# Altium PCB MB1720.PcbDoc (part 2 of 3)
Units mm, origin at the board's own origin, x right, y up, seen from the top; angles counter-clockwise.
Board outline 62.4 x 34.09 mm, 4 copper layers (Top Layer, MidLayer 1, MidLayer 2, Bottom Layer), stack 1.594 mm thick; 82 components, 66 nets, 241 pads, 1258 vias.
Unrouted connection lines stored in the file: 1.
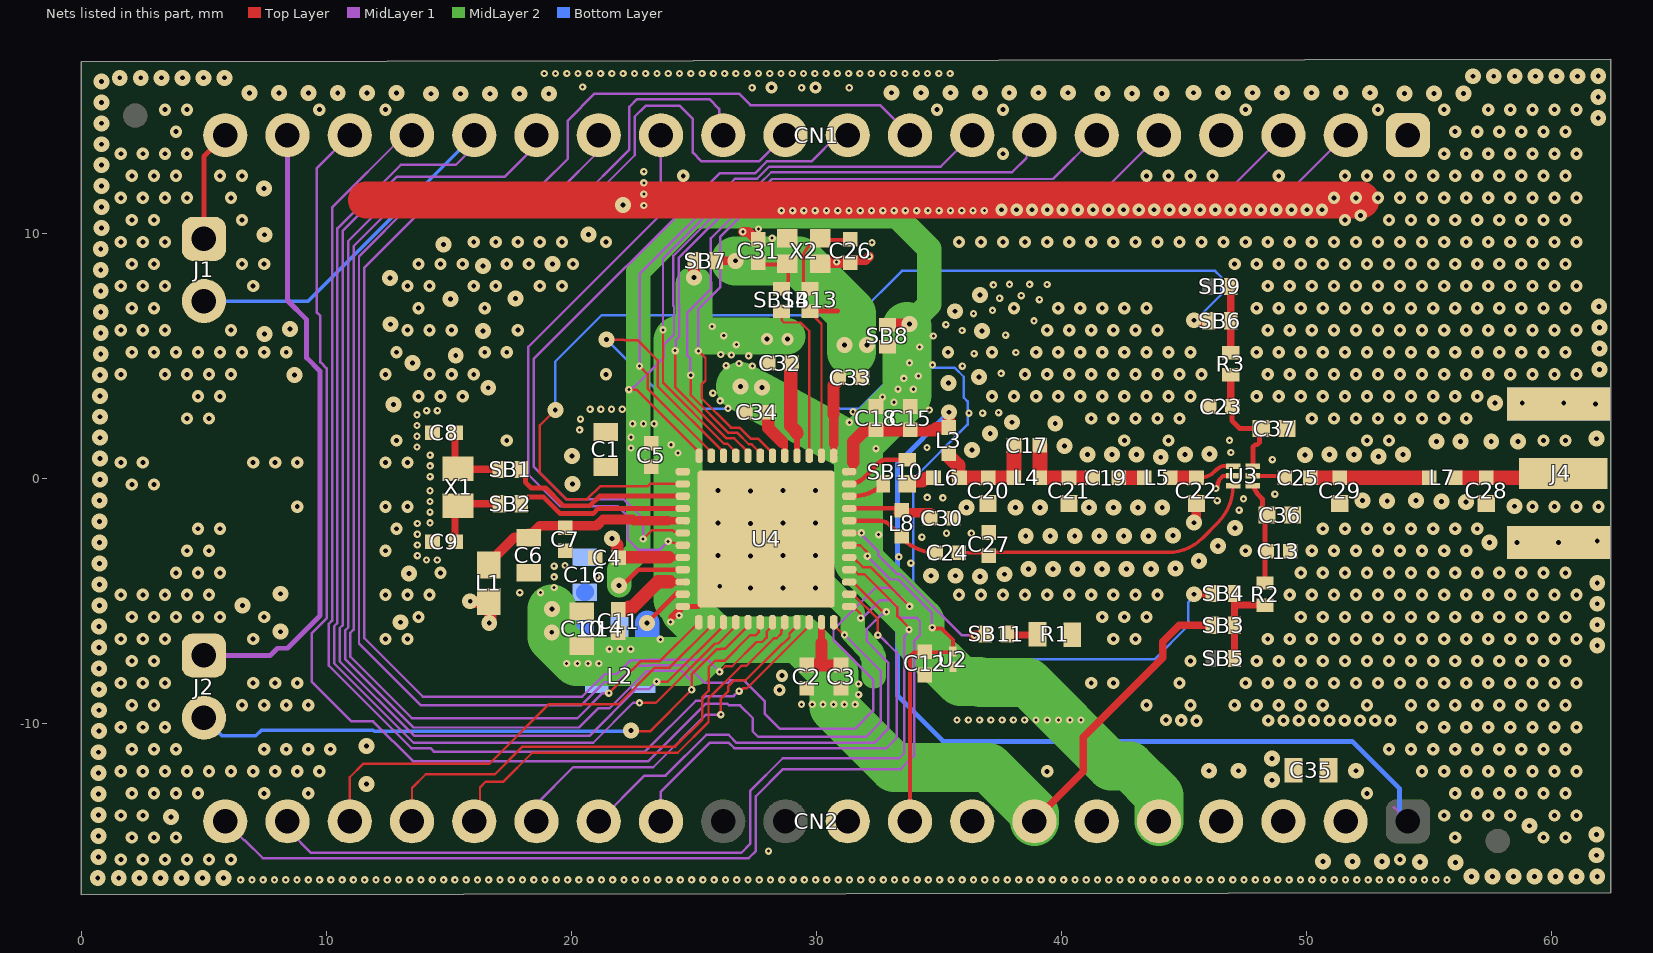
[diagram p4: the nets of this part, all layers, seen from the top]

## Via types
v1: diameter 0.5, hole 0.2, Top Layer to Bottom Layer, 667 vias
v2: diameter 0.3, hole 0.125, Top Layer to MidLayer 1, 336 vias
v3: diameter 0.65, hole 0.2, Top Layer to Bottom Layer, 255 vias

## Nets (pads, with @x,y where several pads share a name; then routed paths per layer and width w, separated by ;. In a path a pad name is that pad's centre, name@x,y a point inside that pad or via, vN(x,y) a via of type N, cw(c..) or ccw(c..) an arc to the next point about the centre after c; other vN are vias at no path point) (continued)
GND: C1.1 C2.1 C3.1 C4.1 C5.1 C6.2 C7.2 C8.2 C9.2 C10.2 C11.2 C12.2 C13.1 C14.2 C15.2 C16.2 C18.1 C20.2 C21.1 C22.1 C23.1 C26.2 C27.1 C28.2 C29.2 C30.1 C31.2 C32.1 C33.1 C34.1 C35.2 C36.1 C37.1 CN1.1 CN1.4 CN2.2 CN2.4 CN2.6 CN2.8 CN2.10 J4.2 R1.1 U2.2 U3.2 U4.48 U4.49 X2.2 X2.4 | length 57
  Top Layer w0.1: CN1.4@46.487,13.977 CN1.4@46.51,14
  Top Layer w0.15: U3.2@46.706,0.1 U3.2@47,0.1
  Top Layer w0.18: v2@46.362,-0.306 cw(c46.706,-0.306) 46.42,-0.116 46.42,-0.072 46.584,0.092 46.706,0.092 U3.2@46.706,0.1
  Top Layer w0.2: U4.48@24.541,-5.231 25.166,-5.231 27.918,-2.479 U4.49@27.94,-2.479
  Top Layer w0.3: 24.1,-5.671 24.391,-5.381 24.391,-5.231 U4.48@24.541,-5.231 ; X2.4@30.15,8.75 X2.4@30.225,8.825
  Top Layer w0.4: v2(26.99,10.061) 27.214,10.061 27.55,9.725 C31.2@27.625,9.725 ; C26.2@31.375,8.825 31.45,8.9 32.004,8.9 v2(32.153,9.049) ; v3@45.481,-1.602 45.481,-1.51 45.493,-1.498 45.493,-0.832 C22.1@45.5,-0.825
  Top Layer w0.5: X2.4@30.225,8.825 C26.2@31.375,8.825 ; C35.2@50.884,-12.056 C35.2@50.884,-11.918 ; CN2.2@51.341,-13.751 CN2.2@51.59,-14
  Top Layer w1.5: 11.629,11.36 16.197,11.359 ; 15.984,11.359 v1@52.229,11.359
  MidLayer 2 w1: 29.684,-3.689 31.485,-5.491 31.485,-6.267 32.252,-7.096 32.252,-7.211 32.325,-7.285 32.325,-8.08 ; CN2.6@41.43,-14 CN2.6@41.43,-13.661
  other v1: 1.608,-15.557 2.508,-15.557 3.408,-15.557 4.308,-15.557 5.208,-15.557 6.108,-15.557 53.809,-15.557 2.058,-14.657 2.958,-14.657 3.858,-14.657 56.059,-14.657 59.659,-14.657 60.559,-14.657 1.608,-13.757 2.508,-13.757 55.609,-13.757 56.509,-13.757 57.409,-13.757 58.309,-13.757 60.109,-13.757 61.009,-13.757 2.058,-12.857 2.958,-12.857 3.858,-12.857 4.758,-12.857 7.458,-12.857 9.258,-12.857 52.459,-12.857 56.059,-12.857 56.959,-12.857 57.859,-12.857 58.759,-12.857 59.659,-12.857 60.559,-12.857 1.608,-11.957 2.508,-11.957 3.408,-11.957 4.308,-11.957 5.208,-11.957 6.108,-11.957 7.008,-11.957 7.908,-11.957 8.808,-11.957 9.708,-11.957 39.409,-11.957 54.709,-11.957 55.609,-11.957 56.509,-11.957 57.409,-11.957 58.309,-11.957 59.209,-11.957 60.109,-11.957 61.009,-11.957 2.058,-11.057 2.958,-11.057 3.858,-11.057 7.458,-11.057 8.358,-11.057 9.258,-11.057 10.158,-11.057 53.359,-11.057 54.259,-11.057 55.159,-11.057 56.059,-11.057 56.959,-11.057 57.859,-11.057 58.759,-11.057 59.659,-11.057 60.559,-11.057 1.608,-10.157 2.508,-10.157 3.408,-10.157 54.709,-10.157 55.609,-10.157 56.509,-10.157 57.409,-10.157 58.309,-10.157 59.209,-10.157 60.109,-10.157 61.009,-10.157 45.505,-9.896 44.258,-9.86 44.882,-9.878 48.432,-9.88 49.055,-9.88 49.678,-9.88 50.302,-9.88 50.925,-9.88 51.548,-9.88 52.171,-9.88 52.794,-9.88 53.417,-9.88 2.058,-9.257 2.958,-9.257 6.558,-9.257 7.458,-9.257 8.358,-9.257 9.258,-9.257 43.459,-9.257 45.259,-9.257 47.059,-9.257 47.959,-9.257 48.859,-9.257 49.759,-9.257 50.659,-9.257 52.459,-9.257 54.259,-9.257 55.159,-9.257 56.059,-9.257 56.959,-9.257 57.859,-9.257 58.759,-9.257 59.659,-9.257 60.559,-9.257 1.608,-8.357 2.508,-8.357 3.408,-8.357 7.008,-8.357 7.908,-8.357 8.808,-8.357 41.209,-8.357 42.109,-8.357 44.809,-8.357 47.509,-8.357 48.409,-8.357 49.309,-8.357 50.209,-8.357 51.109,-8.357 52.009,-8.357 52.909,-8.357 53.809,-8.357 54.709,-8.357 55.609,-8.357 56.509,-8.357 57.409,-8.357 58.309,-8.357 59.209,-8.357 60.109,-8.357 61.009,-8.357 2.058,-7.457 2.958,-7.457 45.259,-7.457 47.959,-7.457 48.859,-7.457 49.759,-7.457 50.659,-7.457 51.559,-7.457 52.459,-7.457 53.359,-7.457 54.259,-7.457 55.159,-7.457 56.059,-7.457 56.959,-7.457 57.859,-7.457 58.759,-7.457 59.659,-7.457 60.559,-7.457 1.608,-6.557 2.508,-6.557 3.408,-6.557 7.008,-6.557 12.408,-6.557 13.309,-6.557 42.109,-6.557 43.009,-6.557 48.409,-6.557 49.309,-6.557 50.209,-6.557 51.109,-6.557 52.009,-6.557 52.909,-6.557 53.809,-6.557 54.709,-6.557 55.609,-6.557 56.509,-6.557 57.409,-6.557 58.309,-6.557 59.209,-6.557 60.109,-6.557 61.009,-6.557 2.058,-5.657 2.958,-5.657 3.858,-5.657 4.758,-5.657 5.658,-5.657 7.458,-5.657 13.759,-5.657 41.659,-5.657 42.559,-5.657 43.459,-5.657 49.759,-5.657 50.659,-5.657 51.559,-5.657 52.459,-5.657 53.359,-5.657 54.259,-5.657 55.159,-5.657 56.059,-5.657 56.959,-5.657 57.859,-5.657 58.759,-5.657 59.659,-5.657 60.559,-5.657 1.608,-4.757 2.508,-4.757 3.408,-4.757 4.308,-4.757 5.208,-4.757 12.408,-4.757 13.309,-4.757 14.209,-4.757 35.809,-4.757 36.709,-4.757 37.609,-4.757 38.509,-4.757 39.409,-4.757 40.309,-4.757 41.209,-4.757 42.109,-4.757 43.009,-4.757 43.909,-4.757 49.309,-4.757 50.209,-4.757 51.109,-4.757 52.009,-4.757 52.909,-4.757 53.809,-4.757 54.709,-4.757 55.609,-4.757 56.509,-4.757 57.409,-4.757 58.309,-4.757 59.209,-4.757 60.109,-4.757 61.009,-4.757 3.858,-3.857 4.758,-3.857 5.658,-3.857 14.659,-3.857 49.759,-3.857 50.659,-3.857 51.559,-3.857 52.459,-3.857 53.359,-3.857 54.259,-3.857 55.159,-3.857 56.059,-3.857 56.959,-3.857 57.859,-3.857 58.759,-3.857 59.659,-3.857 60.559,-3.857 4.308,-2.957 5.208,-2.957 12.408,-2.957 47.509,-2.957 50.209,-2.957 51.109,-2.957 52.009,-2.957 52.909,-2.957 53.809,-2.957 54.709,-2.957 55.609,-2.957 56.509,-2.957 4.758,-2.057 5.658,-2.057 12.859,-2.057 50.659,-2.057 51.559,-2.057 52.459,-2.057 53.359,-2.057 54.259,-2.057 55.159,-2.057 56.059,-2.057 56.959,-2.057 8.808,-1.157 12.408,-1.157 13.309,-1.157 59.209,-1.157 60.109,-1.157 61.009,-1.157 61.909,-1.157 2.058,-0.257 2.958,-0.257 1.608,0.643 2.508,0.643 7.008,0.643 7.908,0.643 8.808,0.643 12.408,0.643 13.309,0.643 12.859,1.543 17.359,1.543 42.559,1.543 44.359,1.543 52.459,1.543 53.359,1.543 59.659,1.543 60.559,1.543 4.308,2.443 5.208,2.443 41.209,2.443 42.109,2.443 43.009,2.443 43.909,2.443 44.809,2.443 50.209,2.443 51.109,2.443 52.009,2.443 52.909,2.443 53.809,2.443 54.709,2.443 55.609,2.443 56.509,2.443 4.758,3.343 5.658,3.343 13.759,3.343 14.659,3.343 15.559,3.343 37.159,3.343 38.059,3.343 38.959,3.343 39.859,3.343 40.759,3.343 41.659,3.343 42.559,3.343 43.459,3.343 44.359,3.343 45.259,3.343 47.959,3.343 48.859,3.343 49.759,3.343 50.659,3.343 51.559,3.343 52.459,3.343 53.359,3.343 54.259,3.343 55.159,3.343 56.059,3.343 56.959,3.343 1.608,4.243 3.408,4.243 4.308,4.243 5.208,4.243 6.108,4.243 12.408,4.243 14.209,4.243 15.109,4.243 16.009,4.243 21.409,4.243 38.509,4.243 39.409,4.243 40.309,4.243 41.209,4.243 42.109,4.243 43.009,4.243 43.909,4.243 44.809,4.243 45.709,4.243 48.409,4.243 49.309,4.243 50.209,4.243 51.109,4.243 52.009,4.243 52.909,4.243 53.809,4.243 54.709,4.243 55.609,4.243 56.509,4.243 57.409,4.243 58.309,4.243 59.209,4.243 60.109,4.243 61.009,4.243 2.058,5.143 2.958,5.143 3.858,5.143 4.758,5.143 5.658,5.143 6.558,5.143 7.458,5.143 8.358,5.143 12.859,5.143 16.459,5.143 17.359,5.143 35.359,5.143 37.159,5.143 38.959,5.143 39.859,5.143 40.759,5.143 41.659,5.143 42.559,5.143 43.459,5.143 44.359,5.143 45.259,5.143 47.959,5.143 48.859,5.143 49.759,5.143 50.659,5.143 51.559,5.143 52.459,5.143 53.359,5.143 54.259,5.143 55.159,5.143 56.059,5.143 56.959,5.143 57.859,5.143 58.759,5.143 59.659,5.143 60.559,5.143 1.608,6.043 2.508,6.043 3.408,6.043 6.108,6.043 13.309,6.043 14.209,6.043 15.109,6.043 17.809,6.043 39.409,6.043 40.309,6.043 41.209,6.043 42.109,6.043 43.009,6.043 43.909,6.043 48.409,6.043 49.309,6.043 50.209,6.043 51.109,6.043 52.009,6.043 52.909,6.043 53.809,6.043 54.709,6.043 55.609,6.043 56.509,6.043 57.409,6.043 58.309,6.043 59.209,6.043 60.109,6.043 61.009,6.043 2.058,6.943 2.958,6.943 13.759,6.943 16.459,6.943 38.059,6.943 39.859,6.943 40.759,6.943 41.659,6.943 42.559,6.943 43.459,6.943 47.959,6.943 48.859,6.943 49.759,6.943 50.659,6.943 51.559,6.943 52.459,6.943 53.359,6.943 54.259,6.943 55.159,6.943 56.059,6.943 56.959,6.943 57.859,6.943 58.759,6.943 59.659,6.943 60.559,6.943 1.608,7.843 2.508,7.843 3.408,7.843 7.008,7.843 13.309,7.843 14.209,7.843 16.009,7.843 16.909,7.843 18.709,7.843 19.609,7.843 48.409,7.843 49.309,7.843 50.209,7.843 51.109,7.843 52.009,7.843 52.909,7.843 53.809,7.843 54.709,7.843 55.609,7.843 56.509,7.843 57.409,7.843 58.309,7.843 59.209,7.843 60.109,7.843 61.009,7.843 2.058,8.743 2.958,8.743 6.558,8.743 7.458,8.743 13.759,8.743 14.659,8.743 15.559,8.743 17.359,8.743 18.259,8.743 20.059,8.743 47.059,8.743 47.959,8.743 48.859,8.743 49.759,8.743 50.659,8.743 51.559,8.743 52.459,8.743 53.359,8.743 54.259,8.743 55.159,8.743 56.059,8.743 56.959,8.743 57.859,8.743 58.759,8.743 59.659,8.743 60.559,8.743 1.608,9.643 2.508,9.643 3.408,9.643 16.009,9.643 16.909,9.643 17.809,9.643 18.709,9.643 19.609,9.643 21.409,9.643 35.809,9.643 36.709,9.643 37.609,9.643 38.509,9.643 39.409,9.643 40.309,9.643 41.209,9.643 42.109,9.643 43.009,9.643 43.909,9.643 44.809,9.643 45.709,9.643 46.609,9.643 47.509,9.643 48.409,9.643 49.309,9.643 50.209,9.643 51.109,9.643 52.009,9.643 52.909,9.643 53.809,9.643 54.709,9.643 55.609,9.643 56.509,9.643 57.409,9.643 58.309,9.643 59.209,9.643 60.109,9.643 61.009,9.643 2.058,10.543 2.958,10.543 6.558,10.543 51.559,10.543 53.359,10.543 54.259,10.543 55.159,10.543 56.059,10.543 56.959,10.543 57.859,10.543 58.759,10.543 59.659,10.543 60.559,10.543 52.202,10.719 37.542,10.956 38.165,10.956 38.788,10.956 39.412,10.956 40.035,10.956 40.658,10.956 41.281,10.956 41.904,10.956 42.527,10.956 43.15,10.956 43.773,10.956 44.397,10.956 45.02,10.956 45.643,10.956 46.266,10.956 46.889,10.956 47.512,10.956 48.135,10.956 48.759,10.956 49.382,10.956 50.005,10.956 50.628,10.956 1.608,11.443 2.508,11.443 3.408,11.443 4.308,11.443 6.108,11.443 51.109,11.443 52.009,11.443 52.909,11.443 53.809,11.443 54.709,11.443 55.609,11.443 56.509,11.443 57.409,11.443 58.309,11.443 59.209,11.443 60.109,11.443 61.009,11.443 2.058,12.343 2.958,12.343 3.858,12.343 5.658,12.343 6.558,12.343 24.559,12.343 43.459,12.343 44.359,12.343 45.259,12.343 46.159,12.343 48.859,12.343 51.559,12.343 52.459,12.343 53.359,12.343 54.259,12.343 55.159,12.343 56.059,12.343 56.959,12.343 57.859,12.343 58.759,12.343 59.659,12.343 60.559,12.343 1.608,13.243 2.508,13.243 3.408,13.243 4.308,13.243 37.609,13.243 55.609,13.243 56.509,13.243 57.409,13.243 58.309,13.243 59.209,13.243 60.109,13.243 61.009,13.243 3.858,14.143 56.059,14.143 56.959,14.143 57.859,14.143 58.759,14.143 59.659,14.143 60.559,14.143 3.408,15.043 4.308,15.043 9.708,15.043 12.408,15.043 34.909,15.043 37.609,15.043 47.509,15.043 52.909,15.043 55.609,15.043 57.409,15.043 58.309,15.043 59.209,15.043 60.109,15.043 61.009,15.043 28.159,15.943 29.959,15.943
  other v2: 6.5,-16.387 6.96,-16.387 7.42,-16.387 7.88,-16.387 8.34,-16.387 8.8,-16.387 9.26,-16.387 9.72,-16.387 10.18,-16.387 10.64,-16.387 11.1,-16.387 11.56,-16.387 12.02,-16.387 12.48,-16.387 12.94,-16.387 13.4,-16.387 13.86,-16.387 14.32,-16.387 14.78,-16.387 15.24,-16.387 15.7,-16.387 16.161,-16.387 16.621,-16.387 17.081,-16.387 17.541,-16.387 18.001,-16.387 18.461,-16.387 18.921,-16.387 19.381,-16.387 19.841,-16.387 20.301,-16.387 20.761,-16.387 21.221,-16.387 21.681,-16.387 22.141,-16.387 22.601,-16.387 23.061,-16.387 23.521,-16.387 23.981,-16.387 24.441,-16.387 24.901,-16.387 25.361,-16.387 25.821,-16.387 26.281,-16.387 26.742,-16.387 27.202,-16.387 27.662,-16.387 28.122,-16.387 28.582,-16.387 29.042,-16.387 29.502,-16.387 29.962,-16.387 30.422,-16.387 30.882,-16.387 31.342,-16.387 31.802,-16.387 32.262,-16.387 32.722,-16.387 33.182,-16.387 33.642,-16.387 34.102,-16.387 34.562,-16.387 35.022,-16.387 35.482,-16.387 35.942,-16.387 36.402,-16.387 36.863,-16.387 37.323,-16.387 37.783,-16.387 38.243,-16.387 38.703,-16.387 39.163,-16.387 39.623,-16.387 40.083,-16.387 40.543,-16.387 41.003,-16.387 41.463,-16.387 41.923,-16.387 42.383,-16.387 42.843,-16.387 43.303,-16.387 43.763,-16.387 44.223,-16.387 44.683,-16.387 45.143,-16.387 45.603,-16.387 46.063,-16.387 46.523,-16.387 46.984,-16.387 47.444,-16.387 47.904,-16.387 48.364,-16.387 48.824,-16.387 49.284,-16.387 49.744,-16.387 50.204,-16.387 50.664,-16.387 51.124,-16.387 51.584,-16.387 52.044,-16.387 52.504,-16.387 52.964,-16.387 53.424,-16.387 53.884,-16.387 54.344,-16.387 54.804,-16.387 55.264,-16.387 55.724,-16.387 28.038,-15.213 35.732,-9.861 36.192,-9.861 36.652,-9.861 37.112,-9.861 37.572,-9.861 38.032,-9.861 38.492,-9.861 38.952,-9.861 39.412,-9.861 39.872,-9.861 40.332,-9.861 40.792,-9.861 29.385,-9.223 29.822,-9.223 30.26,-9.223 30.697,-9.223 31.134,-9.223 31.572,-9.223 31.718,-8.832 31.718,-8.396 19.803,-7.561 20.24,-7.561 20.678,-7.561 21.115,-7.561 21.543,-6.969 21.98,-6.969 22.417,-6.969 23.627,-6.571 24.043,-5.865 24.391,-5.6 17.887,-4.666 18.737,-4.666 19.293,-4.458 19.293,-4.021 21.045,-3.996 19.293,-3.584 19.734,-3.559 33.846,-3.46 14.083,-3.337 14.521,-3.337 33.355,-3.207 13.708,-3.159 13.708,-2.721 34.296,-2.403 32.533,-2.297 13.708,-2.284 35.3,-2.244 36.316,-2.244 13.708,-1.847 14.226,-1.82 14.226,-1.383 47.242,-1.302 14.226,-0.945 46.349,-0.914 47.423,-0.837 35.15,-0.798 34.515,-0.781 48.702,-0.648 14.226,-0.508 46.294,-0.418 14.229,0.067 14.229,0.505 48.597,0.76 14.229,0.942 24.344,1.033 46.903,1.051 32.427,1.212 22.429,1.237 34.508,1.253 13.697,1.278 24.062,1.368 46.848,1.547 22.429,1.674 13.697,1.715 20.33,1.977 13.697,2.153 22.497,2.226 22.934,2.226 23.372,2.226 31.338,2.284 20.368,2.413 13.697,2.59 36.221,2.66 36.778,2.66 37.427,2.678 31.492,2.716 14.089,2.76 14.527,2.76 34.599,2.789 20.757,2.818 21.195,2.818 21.632,2.818 22.069,2.818 26.384,2.855 33.161,3.102 26.064,3.162 32.689,3.312 25.766,3.473 33.32,3.639 33.951,3.632 33.56,4.08 34.153,4.174 37.53,4.279 27.38,4.584 35.945,4.579 26.311,4.599 34.731,4.626 26.842,4.685 33.793,4.709 27.23,4.995 26.519,5.029 26.089,5.052 36.426,5.083 38.13,5.131 34.207,5.359 26.724,5.453 34.764,5.807 26.213,5.818 37.712,5.841 35.937,6.03 25.738,6.196 35.275,6.267 38.871,6.424 36.403,6.716 37.175,6.85 39.092,7.292 37.467,7.347 38.351,7.45 37.214,7.893 37.873,7.914 38.696,7.915 39.41,7.91 30.819,8.826 32.261,9.613 28.189,9.8 27.627,10.173 28.562,10.92 29.022,10.92 29.482,10.92 29.942,10.92 30.402,10.92 30.862,10.92 31.322,10.92 31.782,10.92 32.243,10.92 32.703,10.92 33.163,10.92 33.623,10.92 34.083,10.92 34.543,10.92 35.003,10.92 35.463,10.92 35.923,10.92 36.383,10.92 36.843,10.92 22.953,11.133 22.953,11.593 22.953,12.053 22.953,12.514 27.37,15.937 29.388,15.937 31.333,15.937 20.452,15.965 18.887,16.52 19.347,16.52 19.807,16.52 20.267,16.52 20.727,16.52 21.187,16.52 21.647,16.52 22.107,16.52 22.567,16.52 23.027,16.52 23.487,16.52 23.947,16.52 24.407,16.52 24.867,16.52 25.327,16.52 25.788,16.52 26.248,16.52 26.708,16.52 27.168,16.52 27.628,16.52 28.088,16.52 28.548,16.52 29.008,16.52 29.468,16.52 29.928,16.52 30.388,16.52 30.848,16.52 31.308,16.52 31.768,16.52 32.228,16.52 32.688,16.52 33.148,16.52 33.608,16.52 34.068,16.52 34.528,16.52 34.988,16.52 35.448,16.52
  other v3: 0.668,-16.312 1.523,-16.312 2.378,-16.312 3.233,-16.312 4.088,-16.312 4.942,-16.312 5.797,-16.312 56.727,-16.241 57.581,-16.241 58.436,-16.241 59.291,-16.241 60.146,-16.241 61.001,-16.241 61.855,-16.241 56.073,-15.683 54.621,-15.664 50.67,-15.631 51.87,-15.631 53.07,-15.631 0.693,-15.453 61.831,-15.382 0.693,-14.598 61.831,-14.528 59.094,-14.178 3.657,-13.818 0.693,-13.743 0.693,-12.889 11.635,-12.476 0.693,-12.034 46.017,-11.933 47.217,-11.933 52.017,-11.933 0.693,-11.179 11.636,-10.928 0.717,-10.32 0.717,-9.465 0.717,-8.61 0.717,-7.756 0.717,-6.901 61.855,-6.83 8.13,-6.26 0.717,-6.046 61.855,-5.976 13.029,-5.875 0.741,-5.187 6.57,-5.19 61.855,-5.121 8.131,-4.713 27.306,-4.475 28.631,-4.475 29.956,-4.475 26.048,-4.408 0.741,-4.332 61.855,-4.266 36.67,-4.002 34.672,-3.977 35.67,-3.977 37.666,-3.915 13.376,-3.878 38.643,-3.699 39.643,-3.699 40.643,-3.699 41.643,-3.699 42.643,-3.699 43.643,-3.699 44.642,-3.675 0.741,-3.478 45.596,-3.374 27.306,-3.175 25.981,-3.15 28.631,-3.15 29.956,-3.15 46.382,-2.756 0.741,-2.623 57.461,-2.619 58.579,-2.619 60.27,-2.619 61.855,-2.556 38.536,-2.351 39.536,-2.351 40.536,-2.351 41.536,-2.351 42.536,-2.351 43.536,-2.351 44.536,-2.331 47.071,-2.031 27.306,-1.85 25.981,-1.825 28.631,-1.825 29.956,-1.825 45.405,-1.813 0.741,-1.768 36.118,-1.2 38.11,-1.2 39.11,-1.2 41.11,-1.2 42.11,-1.2 43.11,-1.2 44.106,-1.2 58.484,-1.14 55.492,-0.948 56.499,-0.966 53.284,-0.92 0.741,-0.913 52.284,-0.908 54.463,-0.908 27.306,-0.525 25.981,-0.5 28.631,-0.5 29.956,-0.5 0.766,-0.054 0.766,0.801 44.044,0.86 52.931,0.885 49.935,0.943 41.051,0.974 42.051,0.967 43.051,0.974 45.038,0.974 46.038,0.985 50.935,0.974 51.935,0.974 53.927,0.974 36.343,1.154 40.11,1.315 55.289,1.509 56.276,1.509 57.529,1.509 58.617,1.509 61.819,1.615 0.766,1.655 37.085,1.825 39.738,2.243 37.971,2.288 0.766,2.51 12.736,3.016 61.78,3.027 57.679,3.068 58.796,3.068 60.487,3.068 0.766,3.365 16.602,3.693 35.382,3.882 36.632,4.135 0.766,4.22 8.699,4.215 61.945,4.443 13.504,4.706 15.277,5.018 0.79,5.079 61.945,5.298 7.471,5.891 0.79,5.934 16.39,6.011 36.743,6.011 8.517,6.098 61.945,6.152 12.615,6.284 0.79,6.788 35.643,6.816 61.921,7.011 15.065,7.311 17.715,7.336 36.665,7.477 0.79,7.643 12.597,8.176 0.79,8.498 16.39,8.661 19.232,8.749 0.79,9.353 14.768,9.541 7.472,9.937 20.692,9.952 0.815,10.212 0.815,11.067 22.103,11.158 7.454,11.828 0.815,11.921 0.815,12.776 0.815,13.631 0.815,14.486 61.897,14.709 0.815,15.341 61.897,15.563 14.273,15.691 15.473,15.691 16.673,15.691 17.873,15.691 19.073,15.691 6.862,15.714 8.062,15.714 9.262,15.714 10.462,15.714 11.662,15.714 12.862,15.714 41.673,15.708 42.873,15.708 44.073,15.708 53.998,15.708 55.198,15.708 56.398,15.708 33.063,15.731 34.263,15.731 35.463,15.731 36.663,15.731 37.863,15.731 39.063,15.731 40.263,15.731 45.388,15.731 46.588,15.731 47.788,15.731 48.988,15.731 50.188,15.731 51.388,15.731 52.588,15.731 0.815,16.195 1.567,16.342 2.421,16.342 3.276,16.342 4.131,16.342 4.986,16.342 5.841,16.342 56.778,16.405 57.633,16.405 58.487,16.405 59.342,16.405 60.197,16.405 61.052,16.405 61.897,16.418
NetC6_1: C6.1 C7.1 L1.2 U4.41 | length 8.8
  Top Layer w0.3: 23.949,-1.731 U4.41@24.541,-1.731
  Top Layer w0.4: L1.2@16.624,-3.536 16.624,-3.461 17.663,-2.421 18.086,-2.421 18.249,-2.259 18.386,-2.259 18.707,-1.938 21.029,-1.938 21.289,-1.678 22.494,-1.678 22.547,-1.731 23.949,-1.731
NetC8_1: C8.1 SB1.2 X1.2 | length 3.2
  Top Layer w0.3: C8.1@15.248,1.862 15.248,0.506 X1.2@15.368,0.386 15.393,0.362 SB1.2@17.043,0.362
NetC9_1: C9.1 SB2.2 X1.1 | length 3.2
  Top Layer w0.3: C9.1@15.248,-2.589 15.248,-1.234 X1.1@15.368,-1.114 15.443,-1.039 SB2.2@17.043,-1.039
NetC13_2: C13.2 C36.2 R2.1 U3.4 | length 4.4
  Top Layer w0.2: U3.4@47.8,-0.3 47.987,-0.3 U3.4@48,-0.313 ; U3.4@47.829,-0.358 48,-0.654 48.196,-0.85 48.196,-1.32 C36.2@48.376,-1.5 48.297,-1.58 48.297,-2.973 48.297,-4.267 R2.1@48.303,-4.273
NetC15_1: C15.1 C18.2 L3.2 U4.24 | length 42.8
  Top Layer w0.3: U4.24@31.338,0.269 31.488,0.269 31.488,0.563
  Top Layer w0.5: 31.5,0.653 31.5,1.496 31.954,1.95 32.423,1.95 33.698,1.95 34.787,1.95 34.887,2.05 35.388,2.05 35.398,2.06 v3(35.398,2.693)
  MidLayer 1 w0.1: 53.554,-13.424 54.13,-14
  Bottom Layer w0.2: v3(35.398,2.693) 33.306,0.601 33.306,-8.874 35.165,-10.732 51.859,-10.732 53.78,-12.654 53.78,-13.65 54.13,-14
NetC17_1: C17.1 C20.1 L3.1 L4.1 L6.1 | length 4.7
  Top Layer w0.6: L3.1@35.388,1.04 ccw(c35.7,1.04) 35.48,0.819 35.778,0.521 35.778,0.044 L6.1@35.803,0.019 ; L6.1@35.878,0.02 C20.1@37,0.02 37.879,0.02 L4.1@37.998,0.139 ; L4.1@38.051,0.02 38.057,0.025 C17.1@38.057,1.344
NetC17_2: C17.2 C19.2 C21.2 L4.2 | length 3.5
  Top Layer w0.6: C17.2@39.106,1.345 39.116,1.335 39.116,0.024 L4.2@39.111,0.02 ; L4.2@39.161,0.048 39.184,0.025 C21.2@40.299,0.025 C19.2@41.274,0.025
NetC19_1: C19.1 L5.1 | length 1
  Top Layer w0.6: C19.1@42.324,0.025 L5.1@43.32,0.025
NetC22_2: C22.2 L5.2 U3.1 | length 2.7
  Top Layer w0.16: C22.2@45.5,0.075 ccw(c45.627,0.202) 45.503,0.072 ccw(c45.627,0.202) 45.627,0.022 ccw(c45.627,0.891) 45.917,0.072 ccw(c45.627,0.891) 46.241,0.277 46.314,0.35 cw(c46.677,-0.012) 46.677,0.5 U3.1@47,0.5
  Top Layer w0.6: L5.2@44.479,0.025 C22.2@45.5,0.025
NetC23_2: C23.2 C37.2 R3.1 U3.6 | length 4.9
  Top Layer w0.2: C23.2@46.95,2.926 46.95,2.346 47.265,2.031 C37.2@48.142,2.031 48.07,1.958 48.07,1.454 47.983,1.368 47.892,1.368 47.8,1.276 U3.6@47.8,0.564
  Top Layer w0.3: R3.1@46.9,4.226 46.9,2.926 C23.2@46.95,2.926
NetC24_2: C24.2 C27.2 U3.3 | length 12.7
  Top Layer w0.14: C24.2@35.775,-3.035 37.001,-3.035 ccw(c37.001,-3.001) 37.025,-3.025 44.331,-3.025 ccw(c44.331,-1.023) 45.747,-2.439 46.374,-1.811 ccw(c44.863,-0.3) U3.3@47,-0.3 U3.3@47.008,-0.3
NetC25_1: C25.1 U3.5 | length 0.9
  Top Layer w0.19: U3.5@48.088,0.097 C25.1@48.989,0.089
NetC25_2: C25.2 C29.1 L7.1 | length 4.8
  Top Layer w0.6: C25.2@50.15,0.025 51.15,0.025 L7.1@54.945,0.025
NetC26_1: C26.1 SB13.2 X2.1 | length 3.4
  Top Layer w0.12: SB13.2@29.475,7.675 29.475,9.081 cw(c29.791,9.081) 29.568,9.305 cw(c30.295,8.875) 29.697,9.472 X2.1@29.972,9.747
  Top Layer w0.15: X2.1@30.275,9.725 C26.1@31.375,9.725
NetC28_1: C28.1 J4.1 L7.2 | length 3.2
  Top Layer w0.6: L7.2@56.105,0.025 C28.1@57.325,0.025 J4.1@59.259,0.025
NetC31_1: C31.1 SB14.2 X2.3 | length 2.2
  Top Layer w0.1: X2.3@28.775,8.725 X2.3@28.8,8.75
  Top Layer w0.15: C31.1@27.675,8.725 X2.3@28.775,8.725 ; SB14.2@28.85,7.6 X2.3@28.85,8.7
NetL2_2: L2.2 U4.47 | length 4.1
  Top Layer w0.2: v3(23.086,-5.901) 24.29,-4.697 24.507,-4.697 U4.47@24.541,-4.731
  Bottom Layer w1: L2.2@23.035,-7.964 23.086,-7.912 v3(23.086,-5.901)
NetL6_2: L6.2 SB10.2 | length 1.1
  Top Layer w0.5: SB10.2@33.698,-0.225 33.798,-0.125 34.325,-0.125 34.475,0.025 L6.2@34.675,0.025
NetR1_2: R1.2 SB11.1 | length 1.2
  Top Layer w0.3: SB11.1@37.773,-6.392 38.984,-6.392 R1.2@39.011,-6.365
NetR2_2: R2.2 SB3.2 SB4.2 SB5.2 | length 4
  Top Layer w0.3: SB5.2@47.053,-7.348 SB3.2@47.053,-5.999 47.053,-5.299 ; SB4.2@47.053,-4.699 47.053,-5.173 47.053,-5.299 ; R2.2@48.303,-5.173 47.179,-5.173 47.053,-5.299
NetR3_2: R3.2 SB6.2 SB9.2 | length 2.7
  Top Layer w0.3: R3.2@46.9,5.126 46.902,5.128 46.902,6.378 46.95,6.426 46.904,6.472 SB9.2@46.904,7.826
NetSB1_1: SB1.1 U4.39 | length 7.6
  Top Layer w0.2: SB1.1@17.943,0.362 18.118,0.187 18.118,-0.162 18.348,-0.391 18.938,-0.391 19.669,-1.123 20.751,-1.123 21.143,-0.731 U4.39@24.541,-0.731
NetSB2_1: SB2.1 U4.40 | length 7.1
  Top Layer w0.2: SB2.1@17.943,-1.039 17.943,-0.964 18.118,-0.789 18.193,-0.789 18.213,-0.769 18.863,-0.769 19.537,-1.443 20.884,-1.443 21.095,-1.231 U4.40@24.541,-1.231
NetSB10_1: SB10.1 U4.23 | length 2.7
  Top Layer w0.19: U4.23@31.338,-0.231 ccw(c31.338,0.585) 31.915,0.008 32.541,0.634 cw(c32.841,0.335) 32.841,0.758 SB10.1@33.698,0.758
NetSB10_3: SB10.3 U4.22 | length 1.5
  Top Layer w0.19: U4.22@31.494,-0.731 ccw(c31.494,0.996) SB10.3@32.715,-0.225
  Top Layer w0.27: U4.22@31.338,-0.731 U4.22@31.494,-0.731
NetSB11_2: SB11.2 U4.19 | length 7.3
  Top Layer w0.1: U4.19@31.338,-2.231 31.343,-2.226 v2(31.826,-2.226)
  Top Layer w0.4: v2(36.443,-6.409) 36.746,-6.409 SB11.2@36.748,-6.411
  MidLayer 1 w0.1: v2(31.826,-2.226) 31.826,-2.28 31.916,-2.371 31.916,-2.381 32.524,-2.989 32.524,-3.148 33.287,-3.91 33.433,-3.91 35.932,-6.409 v2(36.443,-6.409)
NetSB13_1: SB13.1 U4.26 | length 7.2
  Top Layer w0.1: SB13.1@29.725,6.769 30.2,6.294 U4.26@30.2,0.919
  Top Layer w0.2: SB13.1@29.725,6.825 30.85,6.825
NetSB14_1: SB14.1 U4.27 | length 6.8
  Top Layer w0.1: SB14.1@28.575,6.825 28.575,6.448 28.666,6.358 29.347,6.358 29.7,6.004 U4.27@29.7,0.919
NRST: C12.1 CN2.9 U2.1 U4.18 | length 15.3
  Top Layer w0.1: U4.18@31.338,-2.731 31.782,-2.731 32.074,-3.023 v2(32.074,-3.176)
  Top Layer w0.15: CN2.9@33.81,-14 33.81,-7.251 33.963,-7.099 34.413,-7.099 35.534,-7.099 U2.1@35.563,-7.069 35.563,-6.594 35.101,-6.132 v2@34.758,-6.132
  MidLayer 1 w0.1: v2(32.074,-3.176) 32.074,-3.187 33.018,-4.13 33.341,-4.13 34.692,-5.481 34.692,-6.065 v2(34.72,-6.093)
PA0: CN1.11 U4.7 | length 57.7
  Top Layer w0.1: v2(26.047,-7.896) 26.272,-7.671 26.559,-7.671 27.549,-6.681 27.781,-6.681 27.963,-6.499 27.963,-6.265 28.2,-6.028 U4.7@28.2,-5.878
  MidLayer 1 w0.1: v2(26.047,-7.896) 26.01,-7.859 26.01,-7.852 25.568,-7.41 23.106,-7.41 23.085,-7.432 22.409,-7.432 21.855,-7.986 21.361,-7.986 20.437,-8.909 13.931,-8.909 11.547,-6.526 11.547,8.598 13.919,10.97 20.37,10.97 22.58,13.18 22.58,14.755 23.02,15.195 24.423,15.195 24.95,14.668 24.95,13.287 25.307,12.93 27.655,12.93 28.725,14 CN1.11@28.73,14
PA1: CN2.16 U4.8 | length 17.5
  Top Layer w0.1: CN2.16@16.03,-14 16.265,-13.765 16.265,-12.61 16.5,-12.375 17.225,-12.375 18.4,-11.2 24.336,-11.2 25.59,-9.946 25.59,-8.989 26.925,-7.654 27.131,-7.654 28.261,-6.525 28.375,-6.525 28.55,-6.35 28.55,-6.224 28.7,-6.074 U4.8@28.7,-5.878
PA2: CN2.15 U4.9 | length 15.1
  Top Layer w0.1: v2(26.093,-9.646) 26.093,-8.99 26.389,-8.695 26.389,-8.502 26.653,-8.238 27.111,-8.238 28.607,-6.742 28.642,-6.742 28.894,-6.49 28.894,-6.334 29.2,-6.028 U4.9@29.2,-5.878
  MidLayer 1 w0.1: CN2.15@18.57,-14 18.57,-13.285 20.064,-11.791 23.336,-11.791 25.48,-9.646 v2(26.093,-9.646)
PA3: CN1.17 U4.10 | length 46.6
  Top Layer w0.1: v2@26.856,-8.646 26.839,-8.663 26.919,-8.663 27.006,-8.576 27.152,-8.576 29.7,-6.028 U4.10@29.7,-5.878
  MidLayer 1 w0.1: CN1.17@13.49,14 13.174,14 10.227,11.053 10.227,-5.81 10.1,-5.938 10.1,-7.648 13.462,-11.01 14.242,-11.01 14.384,-11.152 22.999,-11.152 25.073,-9.079 25.276,-9.079 25.468,-8.887 26.613,-8.887 26.812,-8.688 v2(26.839,-8.688)
PA4: CN1.18 U4.12 | length 54.8
  Top Layer w0.1: U4.12@30.7,-5.878 30.7,-5.987 31.099,-6.386 v2(31.14,-6.386)
  MidLayer 1 w0.1: CN1.18@10.95,14 9.609,12.659 9.609,6.758 9.751,6.617 9.751,4.739 10.007,4.482 10.007,-5.719 9.394,-6.332 9.394,-8.296 11.016,-9.918 11.906,-9.918 13.527,-11.54 23.137,-11.54 25.481,-9.196 26.357,-9.196 26.427,-9.267 26.878,-9.267 27.395,-9.784 27.395,-10.326 27.622,-10.553 32.013,-10.553 32.616,-9.949 32.616,-7.863 v2(31.14,-6.386)
PA5: CN2.20 U4.13 | length 41.8
  Top Layer w0.1: U4.13@31.338,-5.231 31.488,-5.231 31.803,-5.545 v2(31.803,-5.706)
  MidLayer 1 w0.1: CN2.20@5.87,-14.425 CN2.20@5.87,-14 6.645,-14.775 6.675,-14.775 7.405,-15.505 18.985,-15.505 27.015,-15.505 27.228,-15.505 27.525,-15.208 27.525,-12.975 28.635,-11.865 33.435,-11.865 33.983,-11.317 33.991,-11.317 33.991,-6.622 34.22,-6.394 34.22,-5.832 34.081,-5.692 33.427,-5.692 33.306,-5.572 33.306,-5.27 33.022,-4.986 32.591,-4.986 31.871,-5.706 v2(31.803,-5.706)
PA6: CN2.13 U4.14 | length 18.7
  Top Layer w0.1: U4.14@31.338,-4.731 31.488,-4.731 32.502,-5.744 v2(32.502,-6.4)
  MidLayer 1 w0.1: CN2.13@23.65,-14 23.65,-12.782 25.636,-10.796 26.426,-10.796 26.646,-11.015 32.847,-11.015 33.271,-10.592 33.271,-7.12 32.552,-6.4 v2(32.502,-6.4)
PA7: CN2.14 U4.15 | length 21.2
  Top Layer w0.1: U4.15@31.338,-4.231 31.488,-4.231 32.67,-5.412 32.81,-5.412 v2(32.848,-5.45)
  MidLayer 1 w0.1: CN2.14@21.11,-14 22.98,-12.13 23.838,-12.13 25.496,-10.472 26.414,-10.472 26.737,-10.795 32.357,-10.795 32.92,-10.232 32.92,-7.517 32.047,-6.644 32.047,-6.155 32.663,-5.54 32.705,-5.54 32.794,-5.45 v2(32.848,-5.45)
PA8: CN2.19 U4.16 | length 37.3
  Top Layer w0.1: U4.16@31.338,-3.731 31.516,-3.731 31.702,-3.917 31.951,-3.917 32.556,-4.522 32.559,-4.522 33.299,-5.262 33.299,-5.622 33.776,-6.1 33.77,-6.106 v2(33.77,-6.175)
  MidLayer 1 w0.1: CN2.19@8.534,-14.362 8.534,-14.446 9.374,-15.285 26.924,-15.285 27.3,-14.909 27.3,-12.747 28.622,-11.425 33.375,-11.425 33.578,-11.222 33.578,-6.449 33.783,-6.244 33.783,-6.188 v2(33.77,-6.175)
PA9: CN1.12 U4.17 | length 71.4
  Top Layer w0.1: U4.17@31.338,-3.231 31.488,-3.231 31.884,-3.626 32.201,-3.626 v2(33.8,-5.225)
  MidLayer 1 w0.1: CN1.12@26.19,14 26.025,14.165 26.025,15.075 25.625,15.475 22.675,15.475 22.36,15.16 22.36,13.41 20.15,11.2 13.473,11.2 11.327,9.054 11.327,-6.747 13.851,-9.27 20.387,-9.27 21.339,-8.319 21.884,-8.319 22.216,-7.986 22.313,-7.986 22.644,-7.655 23.172,-7.655 23.197,-7.63 24.716,-7.63 25.436,-8.35 26.382,-8.35 26.494,-8.238 27.025,-8.238 27.89,-9.103 27.89,-9.614 28.5,-10.224 31.566,-10.224 32.307,-9.483 32.307,-8.217 30.69,-6.6 30.69,-6.182 32.412,-4.46 33.035,-4.46 v2(33.8,-5.225)
PA10: CN1.7 U4.33 | length 27.4
  Top Layer w0.1: v2(23.732,6.055) 23.732,3.907 26.229,1.41 26.36,1.41 26.7,1.069 U4.33@26.7,0.919
  MidLayer 1 w0.1: v2(23.732,6.055) 23.732,8.968 26.768,12.003 27.662,12.003 28.148,12.49 37.981,12.49 38.565,13.073 38.565,13.675 CN1.7@38.89,14 CN1.7@38.466,14
PA11: SB4.1 U4.34 | length 50
  Top Layer w0.1: v3(21.423,5.656) 21.429,5.65 22.133,5.65 22.148,5.635 22.696,5.635 23.512,4.819 23.512,3.758 26.2,1.069 U4.34@26.2,0.919
  Top Layer w0.3: v3(45.398,-4.731) 46.121,-4.731 SB4.1@46.153,-4.699
  Bottom Layer w0.1: v3(21.423,5.656) 24.245,2.834 31.727,2.834 33.399,4.507 35.641,4.507 36.007,4.141 36.007,3.29 36.161,3.137 36.161,2.191 33.95,-0.02 33.95,-6.52 34.817,-7.387 43.791,-7.387 45.162,-6.016 45.162,-5.064 45.398,-4.828 v3(45.398,-4.731)
PA12: CN1.8 U4.35 | length 24.5
  Top Layer w0.1: v2(22.776,4.575) 23.106,4.245 23.106,3.664 25.7,1.069 U4.35@25.7,0.919
  MidLayer 1 w0.1: v2(22.776,4.575) 22.776,8.335 26.665,12.223 27.571,12.223 28.057,12.71 35.06,12.71 CN1.8@36.35,14
PA13: CN1.6 U4.36 | length 29.7
  Top Layer w0.1: v2(22.34,3.618) 22.651,3.618 25.2,1.069 U4.36@25.2,0.919
  MidLayer 1 w0.1: v2(22.34,3.618) 22.395,3.618 22.489,3.713 22.55,3.713 23.766,4.929 23.766,5.453 24.182,5.869 24.182,7.006 24.153,7.035 24.153,9.077 26.859,11.783 27.753,11.783 28.182,12.212 39.642,12.212 CN1.6@41.43,14
PA14: CN1.10 U4.42 | length 28.8
  Top Layer w0.1: v2(22.925,-2.475) 23.275,-2.125 24.131,-2.125 24.182,-2.176 24.404,-2.176 U4.42@24.419,-2.192
  MidLayer 1 w0.1: v2(22.925,-2.475) 22.925,-1.65 22.128,-0.853 19.781,-0.853 18.455,0.473 18.455,4.86 26.039,12.443 27.48,12.443 27.966,12.93 29.79,12.93 30.86,14 CN1.10@31.27,14
PA15: CN1.13 U4.43 | length 24.4
  Top Layer w0.1: v2(23.944,-2.575) U4.43@24.541,-2.731
  MidLayer 1 w0.1: CN1.13@23.65,14 23.65,10.774 18.235,5.359 18.235,0.159 19.534,-1.14 21.878,-1.14 22.302,-1.563 22.302,-2.488 22.739,-2.925 23.594,-2.925 v2(23.944,-2.575)
PB0: CN1.2 U4.30 | length 38.3
  Top Layer w0.1: v2(25.176,5.195) 25.467,4.904 25.467,3.983 25.306,3.821 25.306,3.267 26.502,2.07 26.861,2.07 27.321,1.609 27.626,1.609 28.2,1.035 U4.30@28.2,0.919
  MidLayer 1 w0.1: v2(25.176,5.195) 25.176,6.901 26.073,7.798 26.073,9.86 27.337,11.123 28.035,11.123 28.463,11.552 28.959,11.552 49.142,11.552 CN1.2@51.59,14
PB2: CN1.3 U4.31 | length 35.9
  Top Layer w0.1: v2(24.866,4.204) 24.866,3.395 26.411,1.85 26.77,1.85 27.23,1.389 27.346,1.389 27.7,1.035 U4.31@27.7,0.919
  MidLayer 1 w0.1: v2(24.866,4.204) 24.843,4.227 24.843,4.892 24.726,5.009 24.726,6.762 25.688,7.724 25.688,9.794 27.237,11.343 27.943,11.343 28.372,11.772 46.822,11.772 CN1.3@49.05,14
PB3: CN1.14 U4.1 | length 45.9
  Top Layer w0.1: v2(21.526,-8.769) 22.831,-7.463 23.608,-7.463 U4.1@25.193,-5.878
  MidLayer 1 w0.1: CN1.14@21.11,14 21.11,13.346 19.525,11.761 13.401,11.761 11.107,9.468 11.107,-6.175 10.98,-6.303 10.98,-7.284 13.488,-9.792 20.238,-9.792 21.262,-8.769 v2(21.526,-8.769)
PB4: CN2.18 U4.2 | length 19.3
  Top Layer w0.1: CN2.18@10.95,-14 10.95,-12.2 11.494,-11.656 16.645,-11.656 19.084,-9.217 21.338,-9.217 21.339,-9.219 21.92,-9.219 23.412,-7.726 24.001,-7.726 25.7,-6.028 U4.2@25.7,-5.878
PB5: CN1.15 U4.3 | length 46.3
  Top Layer w0.1: v2(23.475,-8.3) 23.928,-8.3 26.2,-6.028 U4.3@26.2,-5.878
  MidLayer 1 w0.1: CN1.15@18.57,14 18.57,13.606 17.263,12.298 12.858,12.298 10.667,10.108 10.667,-5.993 10.54,-6.121 10.54,-7.466 13.585,-10.512 20.73,-10.512 22.632,-8.609 23.166,-8.609 v2(23.475,-8.3)
PB6: CN1.16 J1.2 U4.4 | length 58.9
  Top Layer w0.1: v2(22.772,-9.161) 23.44,-9.161 25.859,-6.742 25.985,-6.742 26.7,-6.028 U4.4@26.7,-5.878
  MidLayer 1 w0.1: CN1.16@16.03,14 16.03,13.535 15.287,12.792 13.04,12.792 10.447,10.199 10.447,-5.901 10.32,-6.029 10.32,-7.557 13.553,-10.79 20.885,-10.79 22.514,-9.161 v2(22.772,-9.161)
  Bottom Layer w0.15: J1.2@5,7.23 9.26,7.23 CN1.16@16.03,14
PB7: CN1.9 J2.2 U4.5 | length 85.8
  Top Layer w0.1: v3@22.3,-10.325 23.205,-10.325 v2(24.901,-8.629) 24.901,-8.011 25.941,-6.971 26.068,-6.971 26.08,-6.959 26.268,-6.959 27.2,-6.028 U4.5@27.2,-5.878
  MidLayer 1 w0.1: v2(24.901,-8.629) 24.901,-8.27 24.481,-7.85 23.289,-7.85 23.264,-7.875 23.056,-7.875 21.541,-9.39 21.084,-9.39 20.305,-10.169 13.553,-10.169 10.76,-7.375 10.76,-6.212 10.887,-6.084 10.887,9.68 13.236,12.029 18.842,12.029 19.85,13.037 19.85,14.6 20.945,15.695 26.834,15.695 27.302,15.227 32.583,15.227 CN1.9@33.81,14
  Bottom Layer w0.15: J2.2@5,-9.77 5.739,-10.509 7.115,-10.509 7.346,-10.278 11.906,-10.278 11.952,-10.325 v3@22.3,-10.325
  other v3: 22.434,-10.286
PB8: CN2.17 U4.6 | length 19.7
  Top Layer w0.1: CN2.17@13.49,-14 13.49,-12.635 14.05,-12.075 16.875,-12.075 18,-10.95 24.229,-10.95 25.339,-9.84 25.339,-8.928 25.597,-8.67 25.597,-7.71 25.861,-7.446 26.233,-7.446 26.238,-7.451 26.24,-7.451 27.291,-6.4 27.525,-6.4 27.645,-6.28 27.645,-5.932 U4.6@27.7,-5.878
PB12: CN1.5 U4.32 | length 31.2
  Top Layer w0.1: v2(24.226,5.206) 24.226,3.724 26.32,1.63 26.64,1.63 27.2,1.069 U4.32@27.2,0.919
  MidLayer 1 w0.1: v2(24.226,5.206) 24.249,5.228 24.249,5.624 24.402,5.778 24.402,7.097 24.373,7.126 24.373,8.986 26.95,11.563 27.852,11.563 28.281,11.992 41.962,11.992 CN1.5@43.97,14
PC13: SB6.1 U4.38 | length 43
  Top Layer w0.1: v3(19.338,2.794) 18.709,2.165 18.709,0.22 19.781,-0.853 19.978,-0.853 20.639,-0.853 21.175,-0.317 23.12,-0.317 23.206,-0.231 U4.38@24.541,-0.231
  Top Layer w0.5: v3(45.405,6.448) ccw(c45.457,6.5) 45.457,6.426 SB6.1@46.004,6.426
  Bottom Layer w0.1: v3(19.338,2.794) 19.338,4.766 21.224,6.653 31.671,6.653 33.479,8.46 46.265,8.46 46.512,8.213 46.512,7.503 45.457,6.448 v3(45.405,6.448)
RFI_N: C30.2 L8.2 U4.21 | length 3.7
  Top Layer w0.1: U4.21@31.338,-1.231 31.343,-1.226 U4.21@31.344,-1.225 ; 33.169,-1.226 L8.2@33.348,-1.405
  Top Layer w0.17: U4.21@31.343,-1.226 33.169,-1.226
  Top Layer w0.4: L8.2@33.348,-1.405 34.65,-1.405 34.65,-1.635 ccw(c34.63,-1.635) C30.2@34.63,-1.615
RFI_P: C24.1 L8.1 U4.20 | length 4.2
  Top Layer w0.097: L8.1@33.383,-2.302 ccw(c33.475,-2.21) L8.1@33.475,-2.34
  Top Layer w0.1: L8.1@33.4,-2.34 L8.1@33.475,-2.34
  Top Layer w0.166: L8.1@33.36,-2.302 ccw(c34.875,-1.103) C24.1@34.875,-3.035
  Top Layer w0.17: U4.20@31.338,-1.731 32.576,-1.731 cw(c32.576,-2.3) 32.979,-1.898 L8.1@33.383,-2.302
UART_RX: CN1.19 J2.1 | length 25.6
  MidLayer 1 w0.2: J2.1@5,-7.23 7.708,-7.23 8.003,-6.935 8.409,-6.935 9.737,-5.607 9.737,4.37 9.192,4.916 9.192,6.473 8.41,7.254 CN1.19@8.41,14
UART_TX: CN1.20 J1.1 | length 4.6
  Top Layer w0.2: J1.1@5,9.77 5,13.13 CN1.20@5.87,14
VDD: C1.2 C2.2 C3.2 C4.2 C5.2 C35.1 CN2.3 L1.1 U4.11 U4.37 U4.44 | length 8.8
  Top Layer w0.25: 24.1,-3.225 24.535,-3.225 U4.44@24.541,-3.231
  Top Layer w0.3: 30.2,-6.725 U4.11@30.2,-5.878
  Top Layer w0.5: v3(15.866,-5.019) 15.895,-5.048 16.653,-5.048 16.694,-5.089 16.694,-5.711 16.673,-5.733 16.673,-5.876 v3(16.644,-5.905) ; v3(21.649,-2.453) 21.649,-2.493 21.874,-2.719 21.874,-3.216 C4.2@21.899,-3.241 ; C4.2@21.899,-3.225 22.475,-3.225 23.975,-3.225 ; C2.2@29.575,-7.665 29.6,-7.64 30.3,-7.64 ; 30.15,-7.49 30.3,-7.64 ; 30.2,-7.49 30.2,-6.725 ; C3.2@31.025,-7.665 31,-7.64 30.3,-7.64
  Top Layer w0.7: CN2.3@49.05,-14 CN2.3@49.26,-13.79 ; C35.1@49.459,-12.056 C35.1@49.459,-11.918
  other v1: 28.484,-8.637 28.59,-8.053
  other v3: 48.584,-12.32 48.584,-11.432 20.04,-0.228 20.015,0.902
VDDPA: C33.2 SB7.1 SB8.2 U4.25 | length 11.6
  Top Layer w0.25: 30.7,1.4 U4.25@30.7,0.919 U4.25@30.724,0.943
  Top Layer w0.35: SB7.1@26.04,8.885 v3@26.698,8.885
  Top Layer w0.4: 30.7,1.4 30.7,2.955
  Top Layer w0.5: SB7.1@25.977,8.947 SB7.1@26.04,8.885 ; 30.694,2.602 30.694,3.517 30.694,3.794 30.925,4.025 C33.2@30.925,4.1
  MidLayer 2 w2: v3(26.698,8.875) 29.283,8.875 31.426,6.732 31.426,5.163
  other v3: 31.134,5.439 32.059,5.439
VDDRF: C10.1 C11.1 C32.2 CN2.7 SB3.1 SB7.2 U4.28 U4.46 | length 63.7
  Top Layer w0.25: U4.28@29.177,0.943 U4.28@29.2,0.919 29.2,1.84
  Top Layer w0.3: 24.015,-4.231 U4.46@24.541,-4.231 ; CN2.7@38.89,-13.96 40.888,-11.962 40.888,-10.563 44.131,-7.32 44.131,-6.666 44.798,-5.999 SB3.1@46.153,-5.999
  Top Layer w0.4: CN2.7@38.89,-14 CN2.7@38.89,-13.96
  Top Layer w0.5: v3(24.998,8.187) SB7.2@24.998,8.727 ; C32.2@28.95,4.7 C32.2@28.975,4.675
  Top Layer w0.55: C11.1@21.911,-5.382 22.219,-5.382 22.343,-5.259 22.491,-5.259 23.519,-4.231 24.015,-4.231 ; C32.2@28.95,4.7 28.95,2.141 29.153,1.938 29.153,1.906 29.201,1.857 29.201,1.84
  MidLayer 2 w1.5: v3@24.999,7.917 24.999,5.93 25.121,5.808 27.958,5.808 27.967,5.798 v1@28.79,5.798
  MidLayer 2 w1.9: 25.833,-6.581 29.331,-6.581
  MidLayer 2 w2: v3(19.209,-5.337) 19.209,-6.482 20.203,-7.476 24.938,-7.476 25.833,-6.581 24.661,-5.41 24.661,-5.248 24.352,-4.939 24.352,5.62 ; 29.331,-6.581 30.705,-7.956 30.705,-9.342 33.169,-11.806 37.013,-11.806 38.89,-13.683 CN2.7@38.89,-14
  other v1: 27.979,5.686 28.811,5.677
  other v3: 19.192,-6.285
VDDRF1V55: C14.1 C16.1 C34.2 CN2.5 L2.1 SB8.1 U4.29 U4.45 | length 69.2
  Top Layer w0.2: v3@22.025,-4.425 22.719,-3.731 U4.45@24.541,-3.731 ; U4.29@28.65,0.97 U4.29@28.7,0.919
  Top Layer w0.25: U4.29@28.7,0.794 U4.29@28.7,0.919 28.7,1.45
  Top Layer w0.5: C34.2@28,2.7 28.025,2.675 28.025,2.05 28.584,1.491 ; SB8.1@32.887,6.258 32.902,6.273 33.775,6.273 v3(33.79,6.287)
  MidLayer 2 w1: v3(21.94,-4.374) 21.94,-3.737 22.73,-2.948 22.73,8.444 24.976,10.69 33.277,10.69 34.594,9.373 34.594,7.092 v3(33.79,6.287)
  MidLayer 2 w2: v3(26.893,3.747) 27.589,3.37 31.459,1.275 31.718,1.275 31.718,-3.371 34.21,-5.863 34.21,-6.64 35.868,-8.297 36.644,-8.297 36.682,-8.335 38.621,-8.335 42.017,-11.73 42.762,-11.73 43.97,-12.938 CN2.5@43.97,-14 ; 31.718,1.433 33.687,3.402 v3@33.687,6.185
  Bottom Layer w0.7: C14.1@20.531,-6.136 C14.1@20.531,-6.136 C14.1@20.538,-6.128 ; C16.1@20.538,-4.656 C16.1@20.546,-4.648 C16.1@20.559,-4.636
  other v3: 27.77,3.705
pads on no net: CN2.1 Designator1.1 Mire_1.1 MIRE_2.1 Mire_2.1 Mire_3.1
copper on no net: | length 2676.1
  Top Layer w0.025: 86.395,113.85 88.927,116.382 91.975,119.43 95.023,122.478 98.071,125.526 101.119,128.574 104.167,131.622 107.215,134.67 110.263,137.718 113.311,140.766 114.835,142.29 ; 86.395,115.374 87.403,116.382 90.451,119.43 93.499,122.478 96.547,125.526 99.595,128.574 102.643,131.622 105.691,134.67 108.739,137.718 111.787,140.766 114.835,143.814 ; 86.395,116.898 88.927,119.43 91.975,122.478 95.023,125.526 98.071,128.574 101.119,131.622 104.167,134.67 107.215,137.718 110.263,140.766 113.311,143.814 114.835,145.338 ; 86.395,118.422 87.403,119.43 90.451,122.478 93.499,125.526 96.547,128.574 99.595,131.622 102.643,134.67 105.691,137.718 108.739,140.766 111.787,143.814 114.835,146.862 ; 86.395,119.946 88.927,122.478 91.975,125.526 95.023,128.574 98.071,131.622 101.119,134.67 104.167,137.718 107.215,140.766 110.263,143.814 113.311,146.862 ; 86.395,121.47 87.403,122.478 90.451,125.526 93.499,128.574 96.547,131.622 99.595,134.67 102.643,137.718 105.691,140.766 108.739,143.814 111.787,146.862 ; 86.395,122.994 88.927,125.526 91.975,128.574 95.023,131.622 98.071,134.67 101.119,137.718 104.167,140.766 107.215,143.814 110.263,146.862 ; 86.395,124.518 87.403,125.526 90.451,128.574 93.499,131.622 96.547,134.67 99.595,137.718 102.643,140.766 105.691,143.814 108.739,146.862 ; 86.395,126.042 88.927,128.574 91.975,131.622 95.023,134.67 98.071,137.718 101.119,140.766 104.167,143.814 107.215,146.862 ; 86.395,127.566 87.403,128.574 90.451,131.622 93.499,134.67 96.547,137.718 99.595,140.766 102.643,143.814 105.691,146.862 ; 86.395,129.09 88.927,131.622 91.975,134.67 95.023,137.718 98.071,140.766 101.119,143.814 104.167,146.862 ; 86.395,130.614 87.403,131.622 90.451,134.67 93.499,137.718 96.547,140.766 99.595,143.814 102.643,146.862 ; 86.395,132.138 88.927,134.67 91.975,137.718 95.023,140.766 98.071,143.814 101.119,146.862 ; 86.395,133.662 87.403,134.67 90.451,137.718 93.499,140.766 96.547,143.814 99.595,146.862 ; 86.395,135.186 88.927,137.718 91.975,140.766 95.023,143.814 98.071,146.862 ; 86.395,136.71 87.403,137.718 90.451,140.766 93.499,143.814 96.547,146.862 ; 86.395,138.234 88.927,140.766 91.975,143.814 95.023,146.862 ; 86.395,139.758 87.403,140.766 90.451,143.814 93.499,146.862 ; 86.395,141.282 88.927,143.814 91.975,146.862 ; 86.395,142.806 87.403,143.814 90.451,146.862 ; 86.395,144.33 88.927,146.862 ; 86.395,145.854 87.403,146.862 ; 87.403,113.334 90.451,116.382 93.499,119.43 96.547,122.478 99.595,125.526 102.643,128.574 105.691,131.622 108.739,134.67 111.787,137.718 114.835,140.766 ; 88.927,113.334 91.975,116.382 95.023,119.43 98.071,122.478 101.119,125.526 104.167,128.574 107.215,131.622 110.263,134.67 113.311,137.718 114.835,139.242 ; 90.451,113.334 93.499,116.382 96.547,119.43 99.595,122.478 102.643,125.526 105.691,128.574 108.739,131.622 111.787,134.67 114.835,137.718 ; 91.975,113.334 95.023,116.382 98.071,119.43 101.119,122.478 104.167,125.526 107.215,128.574 110.263,131.622 113.311,134.67 114.835,136.194 ; 93.499,113.334 96.547,116.382 99.595,119.43 102.643,122.478 105.691,125.526 108.739,128.574 111.787,131.622 114.835,134.67 ; 95.023,113.334 98.071,116.382 101.119,119.43 104.167,122.478 107.215,125.526 110.263,128.574 113.311,131.622 114.835,133.146 ; 96.547,113.334 99.595,116.382 102.643,119.43 105.691,122.478 108.739,125.526 111.787,128.574 114.835,131.622 ; 98.071,113.334 101.119,116.382 104.167,119.43 107.215,122.478 110.263,125.526 113.311,128.574 114.835,130.098 ; 99.595,113.334 102.643,116.382 105.691,119.43 108.739,122.478 111.787,125.526 114.835,128.574 ; 101.119,113.334 104.167,116.382 107.215,119.43 110.263,122.478 113.311,125.526 114.835,127.05 ; 102.643,113.334 105.691,116.382 108.739,119.43 111.787,122.478 114.835,125.526 ; 104.167,113.334 107.215,116.382 110.263,119.43 113.311,122.478 114.835,124.002 ; 105.691,113.334 108.739,116.382 111.787,119.43 114.835,122.478 ; 107.215,113.334 110.263,116.382 113.311,119.43 114.835,120.954 ; 108.739,113.334 111.787,116.382 114.835,119.43 ; 110.263,113.334 113.311,116.382 114.835,117.906 ; 111.787,113.334 114.835,116.382 ; 113.311,113.334 114.835,114.858
  Top Layer w0.15: 30.925,7.725 32.23,7.725 32.952,8.448 v3(32.952,9.056)
  Top Layer w0.381: -0.45,116.382 9.962,116.382 33.577,116.382 55.415,116.382 71.921,116.382 86.395,116.382 114.835,116.382 ; -0.45,119.43 9.962,119.43 33.577,119.43 55.415,119.43 71.921,119.43 86.395,119.43 114.835,119.43 ; -0.45,122.478 9.962,122.478 33.577,122.478 55.415,122.478 71.921,122.478 86.395,122.478 114.835,122.478 ; -0.45,125.526 9.962,125.526 33.577,125.526 55.415,125.526 71.921,125.526 86.395,125.526 114.835,125.526 ; -0.45,128.574 9.962,128.574 33.577,128.574 55.415,128.574 71.921,128.574 86.395,128.574 114.835,128.574 ; -0.45,131.622 9.962,131.622 33.577,131.622 55.415,131.622 71.921,131.622 86.395,131.622 114.835,131.622 ; -0.45,134.67 9.962,134.67 33.577,134.67 55.415,134.67 71.921,134.67 86.395,134.67 114.835,134.67 ; -0.45,137.718 9.962,137.718 33.577,137.718 55.415,137.718 71.921,137.718 86.395,137.718 114.835,137.718 ; -0.45,140.766 9.962,140.766 33.577,140.766 55.415,140.766 71.921,140.766 86.395,140.766 114.835,140.766 ; -0.45,143.814 9.962,143.814 33.577,143.814 55.415,143.814 71.921,143.814 86.395,143.814 114.835,143.814 ; -0.45,146.862 114.835,146.862 ; 9.962,149.91 9.962,113.334 ; 33.577,149.91 33.577,113.334 ; 55.415,149.91 55.415,113.334 ; 71.921,149.91 71.921,113.334 ; 86.395,149.91 86.395,113.334 ; 9.962,113.334 33.577,113.334 ; 9.962,113.334 -0.45,113.334 -0.45,149.91 114.835,149.91 114.835,113.334 86.395,113.334 ; 33.577,113.334 55.415,113.334 ; 55.415,113.334 71.921,113.334 ; 71.921,113.334 86.395,113.334
  Bottom Layer w0.15: 5,0 14.225,0 25.151,10.925 31.583,10.925 32.952,9.556 v3(32.952,9.056)

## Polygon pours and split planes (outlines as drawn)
GND on Top Layer "TOP_LAYER_GND_P458" (solid, remove dead copper, pour order 458): -0.132,-16.916 -0.132,17.084 62.401,17.084 62.401,-16.989
GND on Top Layer "Top Layer-GND 1" (solid, pour order 448): 393 vertices, not listed, extent 30.119,-4.33 58.376,2.619
GND on Top Layer "Top Layer-GND" (solid, pour order 447): 44.025,-1.164 43.907,-1.213 43.67,-1.244 43.372,-1.244 43.32,-1.251 42.324,-1.251 42.272,-1.244 41.974,-1.244 41.799,-1.221 41.624,-1.244 41.326,-1.244 41.274,-1.251 39.184,-1.251 39.17,-1.249 38.774,-1.249 38.599,-1.226 38.424,-1.249 38.076,-1.249 38.058,-1.252 38.052,-1.252 38.023,-1.256 35.878,-1.256 35.852,-1.252 35.818,-1.255 35.794,-1.25 35.528,-1.25 35.298,-1.219 35.068,-1.25 34.665,-1.25 34.507,-1.371 34.449,-1.395 34.475,-1.415 34.621,-1.605 34.687,-1.766 35.15,-1.766 35.325,-1.789 35.5,-1.766 36.05,-1.766 36.288,-1.797 36.509,-1.889 36.592,-1.953 36.675,-1.942 37.375,-1.942 37.613,-1.973 37.737,-2.025 44.314,-2.025 44.526,-2.004 44.714,-1.947 44.887,-1.855 45.052,-1.719 45.523,-1.248 45.5,-1.251 44.479,-1.251 44.39,-1.239 44.3,-1.233 44.164,-1.206 44.107,-1.187 44.048,-1.175
VDD on Top Layer "TOP_LAYER_VDD_P438" (solid, pour order 438): 48.354,-10.901 49.758,-10.901 50.087,-11.23 50.091,-14.428 49.503,-15.092 48.534,-15.092 48.044,-14.602 48.044,-11.211
VDDRF on Top Layer "TOP_LAYER_VDDRF_P445" (solid, pour order 445): 22.414,-5.688 20.933,-5.688 20.923,-5.678 20.902,-5.698 20.902,-5.793 19.529,-5.793 19.529,-6.519 19.351,-6.697 19.054,-6.697 18.859,-6.503 18.859,-5.156 19.039,-4.953 22.562,-4.953 22.564,-5.537
VDD on Top Layer "TOP_LAYER_VDD_P446" (solid, pour order 446): 19.898,-0.45 20.19,-0.45 ccw(c20.19,-0.226) 20.385,-0.335 20.457,-0.207 cw(c20.981,-0.5) 20.981,0.1 24.379,0.1 cw(c24.55,-0.475) 24.55,0.125 24.55,0.26 24.335,0.475 24.056,0.475 23.755,0.775 22.221,0.775 22.221,0.814 20.927,0.814 cw(c20.927,1.414) 20.403,1.121 20.331,1.249 ccw(c20.136,1.14) 20.136,1.364 19.844,1.364 ccw(c20.35,0.471)
VDD on Top Layer "TOP_LAYER_VDD_P444" (solid, pour order 444): 31.374,-7.201 28.973,-7.202 28.05,-8.022 28.05,-8.88 28.122,-8.952 28.895,-8.952 28.998,-8.849 29,-8.21 29.325,-7.885 31.374,-7.885
VDDRF1V55 on Top Layer "TOP_LAYER_VDDRF1V55_P440" (solid, pour order 440): 27.725,2.35 28.275,2.35 28.275,3.875 ccw(c28.054,3.875) 28.054,4.096 26.496,4.096 ccw(c26.496,3.945) 26.345,3.945 26.345,3.532 ccw(c26.577,3.532) 26.577,3.3 27.475,3.3 27.725,3.05
VDDRF on Top Layer "TOP_LAYER_VDDRF_P439" (solid, pour order 439): 29.225,4.675 29.225,5.814 29.02,6.02 27.753,6.024 27.561,5.833 27.561,5.411 27.67,5.302 28.557,5.302 28.675,5.184 28.675,4.675
VDDPA on Top Layer "TOP_LAYER_VDDPA_P443" (solid, pour order 443): 30.65,4.225 30.65,5.775 30.775,5.9 32.205,5.9 32.625,5.479 32.625,5.155 32.345,4.875 31.45,4.875 31.2,4.625 31.2,4.225
GND on MidLayer 2 "MIDLAYER_2_GND_P453" (solid, remove dead copper, pour order 453): 0,-16.907 0,16.953 62.401,16.953 62.401,-16.907
VDD on MidLayer 2 "MIDLAYER_2_VDD_P452" (solid, remove dead copper, pour order 452): 11.47,-16.883 11.47,-13.769 17.295,0.295 19.074,2.074 32.78,2.074 32.78,-14.99 48.119,-14.99 48.119,-11.259 48.427,-10.952 49.663,-10.951 49.99,-11.279 49.99,-16.904
GND on MidLayer 2 "MIDLAYER_2_GND_P451" (solid, pour order 451): 25.123,0.237 25.123,-5.222 30.97,-5.222 30.97,0.178
GND on Bottom Layer "BOTTOM_LAYER_GND_P457" (solid, remove dead copper, pour order 457): 0.134,-16.891 0.134,17.039 62.401,17.039 62.401,-16.964
VDDPA on Bottom Layer "NONET_L-01_P-001" (solid, pour order 454): 30.067,6.157 30.067,3.095 32.801,3.095 32.801,6.157
VDDRF on Bottom Layer "NONET_L-01_P-001" (solid, pour order 455): 25.151,6.247 25.151,4.369 29.516,4.369 29.516,6.247
VDDRF1V55 on Bottom Layer "NONET_L-01_P-001" (solid, pour order 456): 20.049,-4.278 21.409,-4.278 21.485,-4.202 21.485,-4.053 21.703,-3.834 22.312,-3.834 22.573,-4.095 22.573,-4.812 22.361,-5.024 21.495,-5.024 ccw(c21.495,-5.714) 21.007,-5.226 ccw(c21.237,-5.456) 20.912,-5.456 20.912,-6.671 21.544,-7.357 21.544,-8.791 20.375,-8.791 20.053,-8.47
GND on MidLayer 1 "MIDLAYER_1_GND_P449" (solid, remove dead copper, pour order 449): -0.02,-16.98 -0.02,17 62.401,17 62.401,-17.053

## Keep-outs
Keep-Out Layer:
  lines w1.2: -0.614,-17.583 -0.614,17.619 63.122,17.619 63.122,-17.583 -0.614,-17.583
